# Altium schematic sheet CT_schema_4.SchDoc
size 313 x 200 mm
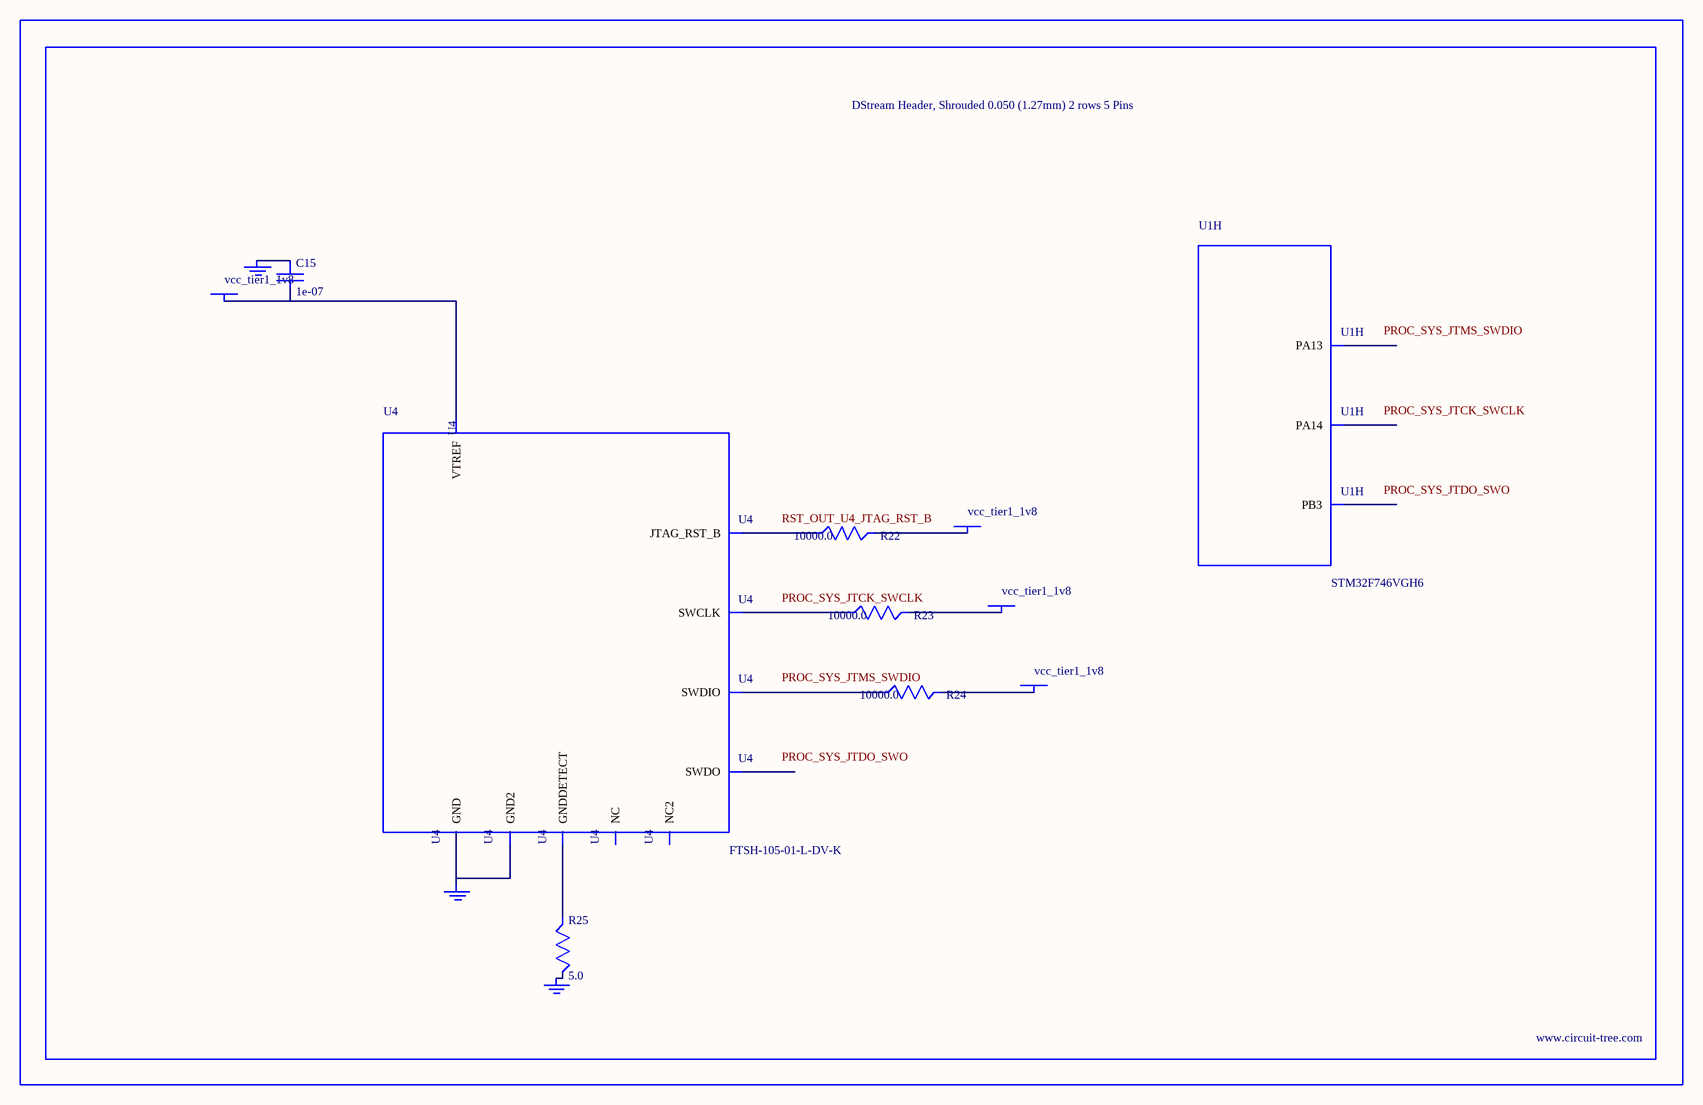
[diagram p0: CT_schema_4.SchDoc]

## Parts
BORDER3  (no value)
C15  1e-07  [C0402]
GND_INSTANCE_3_0  (no value)
GND_INSTANCE_3_1  (no value)
GND_INSTANCE_3_2  (no value)
POWER_INSTANCE_3_0  vcc_tier1_1v8
POWER_INSTANCE_3_1  vcc_tier1_1v8
POWER_INSTANCE_3_2  vcc_tier1_1v8
POWER_INSTANCE_3_3  vcc_tier1_1v8
R22  10000.0  [R0603]
R23  10000.0  [R0603]
R24  10000.0  [R0603]
R25  5.0  [R0603]
U1  STM32F746VGH6  [TFBGA100]  (part H of 10)
U4  FTSH-105-01-L-DV-K  [SAMTEC_FTSH-105-01-L-DV-K]

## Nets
NetC15_1: C15.1 GND_INSTANCE_3_0.0(GND)
NetC15_2: C15.2 POWER_INSTANCE_3_0.0(PWR) U4.1(VTREF)
NetGND_INSTANCE_3_1_0: GND_INSTANCE_3_1.0(GND) R25.2
NetGND_INSTANCE_3_2_0: GND_INSTANCE_3_2.0(GND) U4.3(GND) U4.5(GND2)
NetPOWER_INSTANCE_3_1_0: POWER_INSTANCE_3_1.0(PWR) R24.2
NetPOWER_INSTANCE_3_2_0: POWER_INSTANCE_3_2.0(PWR) R23.2
NetPOWER_INSTANCE_3_3_0: POWER_INSTANCE_3_3.0(PWR) R22.2
NetR22_1: R22.1 U4.10(JTAG_RST_B)
NetR23_1: R23.1 U4.4(SWCLK)
NetR24_1: R24.1 U4.2(SWDIO)
NetR25_1: R25.1 U4.9(GNDDETECT)

Not connected (* = marked no-connect by the designer): U1 A7(PB3) A9(PA14) A10(PA13); U4 6(SWDO) 7(NC) 8(NC2)

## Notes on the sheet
- Labels drawn without touching a wire or pin: PROC_SYS_JTCK_SWCLK, PROC_SYS_JTDO_SWO, PROC_SYS_JTMS_SWDIO, RST_OUT_U4_JTAG_RST_B

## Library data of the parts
BORDER3 = BORDER_PAGE3
C15 = C0402C104K3RACTU
GND_INSTANCE_3_0-GND_INSTANCE_3_2 = GND
POWER_INSTANCE_3_0-POWER_INSTANCE_3_3 = PWR
R22-R24 = RC0603JR-0710KL
R25 = ERJ-3GEYJ5R1V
